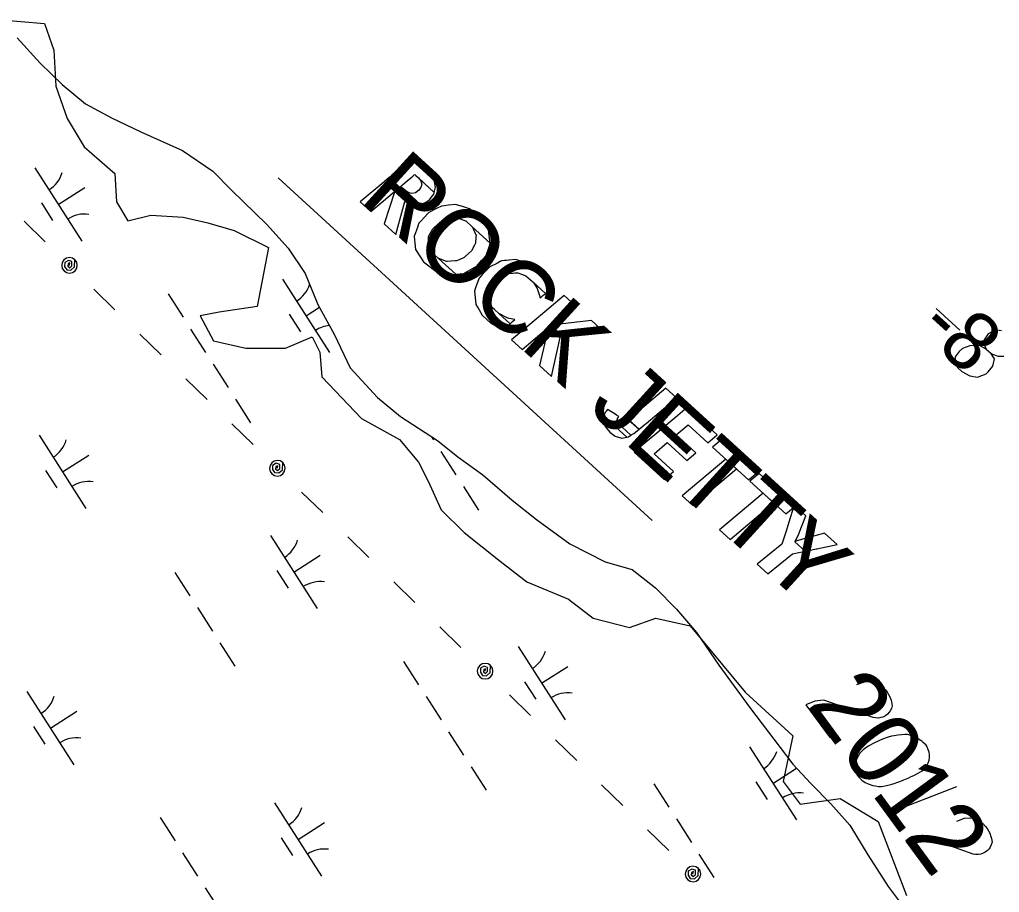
# Model space of a CAD drawing. Extents: x 3962991 to 3983549, y 181631 to 204078.
# Drawn here: x 3976533 to 3977096, y 190286 to 190788 of the extents above; entities that cross this region are included whole.
import ezdxf

# ---------------------------------------------------------------- set-up
doc = ezdxf.new("R2010")
doc.units = 0
for name, color, linetype in [('V-ANNO-MASK', 7, 'Continuous'), ('V-ANNO-MASK2', 7, 'Continuous'), ('V-RIVR-EDGE', 7, 'Continuous'), ('V-RIVR-IDEN', 7, 'Continuous'), ('V-RIVR-RANG', 7, 'Continuous'), ('V-RRAP-FSHR', 7, 'Continuous'), ('V-UTIL-LINE', 7, 'Continuous'), ('V-WETL-SWMP', 7, 'Continuous')]:
    doc.layers.add(name, color=color, linetype=linetype)

msp = doc.modelspace()

# ---------------------------------------------------------------- linework, layer by layer
at = {"layer": 'V-ANNO-MASK2'}
for p, q in [((3977059.67, 190621.74), (3977073.35, 190609.34)), ((3977071.45, 190346.77), (3977030.93, 190331.01))]:
    msp.add_line(p, q, dxfattribs=at)
for points in [[(3976742.01, 190694.45), (3976728.45, 190683.01), (3976734.52, 190677.47), (3976748.08, 190688.91), (3976748.42, 190689.19), (3976755.55, 190682.68), (3976756.57, 190682.19), (3976760.04, 190681.33), (3976763, 190681.68), (3976751.71, 190691.97), (3976751.72, 190691.98), (3976751.91, 190692.14), (3976752.38, 190692.54), (3976752.71, 190692.82), (3976754.11, 190693.99), (3976755.65, 190695.29), (3976755.74, 190695.38), (3976757.37, 190696.74), (3976758.68, 190697.84), (3976758.95, 190698.07), (3976759.55, 190698.57), (3976759.78, 190698.77), (3976759.79, 190698.78), (3976771.03, 190688.53), (3976771.8, 190691.53), (3976770.91, 190695.86), (3976768.19, 190699.86), (3976764.36, 190703.48), (3976758.77, 190708.59), (3976758.68, 190708.52), (3976757.82, 190707.8), (3976755.82, 190706.1), (3976753.71, 190704.33), (3976753.7, 190704.32), (3976753.47, 190704.12), (3976752.87, 190703.61), (3976752.6, 190703.39), (3976751.29, 190702.28), (3976749.67, 190700.92), (3976749.57, 190700.83), (3976748.03, 190699.53), (3976746.64, 190698.36), (3976746.3, 190698.08), (3976745.83, 190697.68), (3976745.65, 190697.52), (3976745.64, 190697.51), (3976743.9, 190696.05), (3976742.58, 190694.94), (3976742.34, 190694.73)], [(3976755.97, 190688.43), (3976754.01, 190689.9), (3976763.02, 190681.68), (3976763.34, 190681.72), (3976764.14, 190681.81), (3976764.53, 190682.04), (3976766.18, 190682.98), (3976768, 190684.03), (3976768.08, 190684.13), (3976768.07, 190684.13), (3976769.41, 190685.75), (3976770.5, 190687.07), (3976770.72, 190687.34), (3976770.94, 190688.19), (3976771.02, 190688.52), (3976761.94, 190696.8), (3976763.32, 190695.13), (3976763.66, 190693.77), (3976763.81, 190693.17), (3976763.32, 190691.31), (3976762.04, 190689.63), (3976761.94, 190689.56), (3976760.28, 190688.36), (3976758.14, 190687.86), (3976757.24, 190688.1)], [(3976760.47, 190698.16), (3976761.95, 190696.8), (3976771.02, 190688.52), (3976771.03, 190688.53)], [(3976748.27, 190688.74), (3976742.24, 190670.43), (3976748.9, 190664.36), (3976754.18, 190683.35), (3976755.55, 190682.68), (3976748.42, 190689.19)], [(3976754, 190689.9), (3976752.6, 190691.16), (3976763, 190681.68), (3976763.02, 190681.68)], [(3976763.16, 190651.2), (3976764.8, 190648.58), (3976771.95, 190643.18), (3976774.95, 190642.38), (3976779.99, 190641.02), (3976783.41, 190641.43), (3976773.5, 190650.47), (3976769.74, 190653.97), (3976767.71, 190658.33), (3976767.71, 190658.45), (3976767.75, 190660.54), (3976767.74, 190660.54), (3976767.79, 190663.18), (3976767.97, 190663.52), (3976768.73, 190664.93), (3976770.18, 190667.62), (3976770.4, 190667.82), (3976770.4, 190667.82), (3976770.92, 190668.3), (3976774.16, 190671.28), (3976774.15, 190671.29), (3976774.21, 190671.33), (3976774.48, 190671.45), (3976777.97, 190673.02), (3976779.16, 190673.55), (3976779.19, 190673.56), (3976782.69, 190673.78), (3976784.3, 190673.88), (3976784.37, 190673.88), (3976789.1, 190672.12), (3976789.13, 190672.11), (3976792.93, 190668.68), (3976803.24, 190659.28), (3976802.71, 190663.76), (3976802.33, 190666.98), (3976799.34, 190671.74), (3976798, 190673.88), (3976797.99, 190673.88), (3976791.23, 190679.14), (3976787.91, 190680.14), (3976783.21, 190681.54), (3976779.29, 190681.12), (3976779.26, 190681.12), (3976779.24, 190681.11), (3976776.74, 190680.84), (3976776.68, 190680.83), (3976775.14, 190680.67), (3976772.74, 190679.44), (3976772.72, 190679.43), (3976771.58, 190678.85), (3976768.24, 190677.14), (3976767.99, 190677.01), (3976767.92, 190676.97), (3976764.93, 190673.77), (3976764.45, 190673.24), (3976764.25, 190673.03), (3976762.23, 190670.85), (3976761.66, 190669.28), (3976761.52, 190668.9), (3976760.79, 190666.89), (3976760.21, 190665.29), (3976760.17, 190665.21), (3976759.49, 190663.31), (3976759.5, 190663.24), (3976759.93, 190659.31), (3976760.34, 190655.7)], [(3976773.62, 190650.43), (3976773.5, 190650.47), (3976783.41, 190641.43), (3976783.48, 190641.44), (3976783.48, 190641.44), (3976785.92, 190641.73), (3976786.04, 190641.74), (3976786.03, 190641.74), (3976788.1, 190641.98), (3976789.93, 190643), (3976790.27, 190643.19), (3976790.26, 190643.19), (3976791.7, 190643.98), (3976794.44, 190645.5), (3976794.71, 190645.65), (3976795.37, 190646.01), (3976798.26, 190649.3), (3976798.31, 190649.35), (3976798.49, 190649.56), (3976800.81, 190652.19), (3976801.24, 190653.42), (3976801.25, 190653.45), (3976802.15, 190656.04), (3976802.55, 190657.23), (3976802.58, 190657.28), (3976803.25, 190659.22), (3976803.24, 190659.24), (3976803.24, 190659.28), (3976792.93, 190668.68), (3976792.95, 190668.62), (3976792.97, 190668.59), (3976795, 190664.19), (3976795.06, 190664.07), (3976794.98, 190662.57), (3976794.81, 190659.32), (3976794.8, 190659.3), (3976794.22, 190658.21), (3976792.52, 190655), (3976792.32, 190654.82), (3976792.27, 190654.76), (3976789.04, 190651.79), (3976788.51, 190651.3), (3976788.22, 190651.17), (3976785.28, 190649.83), (3976783.75, 190649.13), (3976783.24, 190649.1), (3976780.52, 190648.89), (3976778.38, 190648.72), (3976778.16, 190648.8)], [(3976798.66, 190617.87), (3976798.71, 190617.8), (3976803.55, 190613.42), (3976807.98, 190610.81), (3976810.64, 190609.85), (3976810.92, 190609.74), (3976814.61, 190613), (3976808.21, 190618.84), (3976805.67, 190621.22), (3976804.4, 190622.41), (3976803.05, 190625.31), (3976802.37, 190626.77), (3976802.46, 190631.63), (3976803.38, 190633.35), (3976804.85, 190636.06), (3976808.79, 190639.71), (3976808.87, 190639.78), (3976813.82, 190641.99), (3976816.25, 190642.15), (3976817.32, 190642.22), (3976817.73, 190642.24), (3976819.03, 190642.33), (3976821.14, 190641.54), (3976823.79, 190640.55), (3976827.71, 190637.2), (3976835.09, 190630.47), (3976837.28, 190632.25), (3976837.94, 190632.78), (3976836.52, 190636.68), (3976834.32, 190639.86), (3976832.61, 190642.33), (3976832.61, 190642.33), (3976825.85, 190647.59), (3976823.93, 190648.16), (3976819.68, 190649.44), (3976817.83, 190649.99), (3976814.13, 190649.59), (3976813.91, 190649.57), (3976812.51, 190649.42), (3976811.39, 190649.29), (3976810.14, 190649.16), (3976809.76, 190649.11), (3976809.02, 190648.74), (3976807.35, 190647.89), (3976802.63, 190645.47), (3976802.53, 190645.42), (3976798.88, 190641.5), (3976796.85, 190639.3), (3976796.14, 190637.38), (3976794.8, 190633.68), (3976794.57, 190633.05), (3976794.11, 190631.79), (3976794.11, 190631.76), (3976794.11, 190631.69), (3976794.93, 190624.33), (3976794.95, 190624.15), (3976796.83, 190620.97)], [(3976831.56, 190629.23), (3976831.9, 190627.87), (3976832.51, 190628.37), (3976832.74, 190628.56), (3976833.47, 190629.16), (3976834.13, 190629.69), (3976834.96, 190630.37), (3976835.09, 190630.47), (3976827.71, 190637.2), (3976828.04, 190636.68), (3976830.17, 190633.31), (3976830.77, 190631.63), (3976831.43, 190629.74)], [(3976830.72, 190616.59), (3976815.43, 190603.69), (3976821.5, 190598.15), (3976836.8, 190611.05), (3976843.37, 190605.06), (3976843.53, 190605.78), (3976845.03, 190605.94), (3976838.16, 190612.21), (3976851.83, 190623.72), (3976845.75, 190629.26), (3976832.09, 190617.74), (3976831.21, 190617.01)], [(3976808.39, 190618.74), (3976808.21, 190618.84), (3976814.61, 190613), (3976814.64, 190613.04), (3976814.66, 190613.05), (3976815.59, 190613.87), (3976816.06, 190614.29), (3976817.31, 190615.39), (3976814.1, 190616.08), (3976812.89, 190616.34), (3976808.48, 190618.69)], [(3976836.8, 190611.05), (3976831.62, 190588.92), (3976838.46, 190582.69), (3976843.37, 190605.06)], [(3976861.43, 190614.96), (3976838.16, 190612.21), (3976845.03, 190605.94), (3976868.62, 190608.4)], [(3976886.19, 190560.76), (3976882.78, 190557.87), (3976888.83, 190552.35), (3976892.26, 190555.22), (3976892.89, 190555.75), (3976910.28, 190570.41), (3976904.2, 190575.96), (3976886.82, 190561.28)], [(3976891.41, 190543.8), (3976886.06, 190539.28), (3976903.33, 190523.53), (3976908.69, 190528.05), (3976897.44, 190538.31), (3976905, 190544.69), (3976916.25, 190534.43), (3976921.48, 190538.84), (3976910.23, 190549.1), (3976917.05, 190554.85), (3976928.3, 190544.59), (3976933.65, 190549.1), (3976916.39, 190564.84), (3976911.04, 190560.34), (3976904.22, 190554.59), (3976898.98, 190550.18)], [(3976870.32, 190552.72), (3976871.93, 190550.75), (3976875.17, 190548.3), (3976875.64, 190548.16), (3976878.88, 190547.19), (3976879, 190547.22), (3976881.71, 190547.79), (3976868.5, 190559.84), (3976868.34, 190556.94), (3976868.4, 190556.74), (3976869.38, 190553.87)], [(3976868.83, 190560.62), (3976868.49, 190559.85), (3976881.71, 190547.79), (3976882.68, 190547.99), (3976884.07, 190548.89), (3976884.11, 190548.91), (3976876.59, 190555.77), (3976876.19, 190556.77), (3976876.02, 190557.2), (3976876.42, 190558.42), (3976876.45, 190558.51), (3976876.96, 190559.22), (3976877.08, 190559.38), (3976877.26, 190559.62), (3976875.92, 190560.44), (3976875, 190561.01), (3976871.06, 190563.43), (3976870.65, 190563.68), (3976869.95, 190562.74), (3976869.82, 190562.57), (3976869.54, 190562.19), (3976869.52, 190562.16)], [(3976878.12, 190555.01), (3976876.59, 190555.77), (3976884.11, 190548.91), (3976884.52, 190549.17), (3976884.69, 190549.29), (3976885.72, 190549.94), (3976885.79, 190549.99), (3976886.55, 190550.48), (3976886.73, 190550.59), (3976888.83, 190552.35), (3976882.78, 190557.88), (3976880.6, 190556.17), (3976880.44, 190556.05), (3976879.58, 190555.66), (3976879.49, 190555.62), (3976878.32, 190555.1)], [(3976936.46, 190546.54), (3976931.14, 190542.07), (3976951.75, 190523.27), (3976957.07, 190527.75)], [(3976938.67, 190535.2), (3976913.66, 190514.11), (3976919.74, 190508.56), (3976944.76, 190529.66)], [(3976957.9, 190526.99), (3976952.58, 190522.52), (3976973.19, 190503.72), (3976978.51, 190508.19)], [(3976960.11, 190515.65), (3976935.1, 190494.55), (3976941.19, 190489), (3976966.2, 190510.1)], [(3976970.99, 190486.23), (3976956.73, 190474.83), (3976962.82, 190469.27), (3976977.07, 190480.68), (3976977.12, 190480.71), (3976984.34, 190482.24), (3976978.41, 190487.65), (3976979.27, 190489.15), (3976979.32, 190489.28), (3976980.87, 190492.61), (3976980.94, 190492.79), (3976984.73, 190502.52), (3976977.99, 190508.66), (3976974.79, 190498.39), (3976974.73, 190498.21), (3976973.58, 190494.52), (3976973.53, 190494.39), (3976972.98, 190492.6), (3976971.01, 190486.29)], [(3976980.12, 190488.38), (3976978.41, 190487.65), (3976984.34, 190482.24), (3976986.37, 190482.68), (3976986.53, 190482.71), (3976990.75, 190483.6), (3976990.96, 190483.64), (3977002.71, 190486.13), (3976995.54, 190492.66), (3976984.41, 190489.62), (3976984.21, 190489.56), (3976980.25, 190488.43)]]:
    msp.add_lwpolyline(points, close=True, dxfattribs=at)
for points in [[(3977097.27, 190609.01), (3977094.64, 190609.25), (3977091.7, 190608.36), (3977089.52, 190607.13), (3977087.25, 190603.85), (3977086.97, 190601.97), (3977088.44, 190598.49), (3977084.61, 190600.55), (3977079.02, 190600.27), (3977074.8, 190598.76), (3977072.83, 190596.99), (3977070.54, 190594.07), (3977070.53, 190590.52), (3977072.16, 190587.62), (3977074.51, 190585.49), (3977079.11, 190583.1), (3977083.44, 190582.38), (3977088.39, 190584.3), (3977089.64, 190585.29), (3977092.28, 190588.59), (3977093.2, 190592.75), (3977091.18, 190596.01)], [(3977088.44, 190598.49), (3977091.18, 190596.01), (3977092.14, 190595.5), (3977095.37, 190594.35), (3977098.54, 190594.31)], [(3977014.03, 190405.55), (3977018.55, 190407.22), (3977023.31, 190407.43), (3977026.41, 190406.01), (3977028.97, 190404.19), (3977030.6, 190402.52), (3977031.58, 190401.19), (3977033.07, 190398.59), (3977033.71, 190396.6), (3977034.03, 190395.6), (3977034.4, 190393.42), (3977033.92, 190391.84), (3977033.25, 190390.52), (3977032.64, 190389.67), (3977031.77, 190388.62), (3977030.44, 190387.64), (3977028.91, 190386.93), (3977027.91, 190386.61), (3977026.45, 190386.36), (3977024.8, 190386.38), (3977023.41, 190386.59), (3976995.15, 190396.63), (3976989.85, 190396.03), (3976984.8, 190393.97), (3976998.68, 190375.03)], [(3977054.25, 190370.24), (3977053.86, 190370.78), (3977052.42, 190372.18), (3977051.37, 190373.05), (3977050.52, 190373.66), (3977049.01, 190374.6), (3977047.04, 190375.62), (3977045.26, 190376.36), (3977043.22, 190376.92), (3977041.56, 190376.93), (3977039.64, 190376.76), (3977037.72, 190376.58), (3977035.53, 190376.21), (3977034.08, 190375.96), (3977032.08, 190375.32), (3977028.83, 190374.17), (3977024.24, 190372.03), (3977020.65, 190370.22), (3977017.72, 190368.07), (3977015.78, 190366.24), (3977014.16, 190363.41), (3977013.41, 190361.64), (3977012.79, 190359.13), (3977012.89, 190356.75), (3977013.21, 190355.75), (3977014.12, 190353.96), (3977015.1, 190352.62), (3977016.93, 190350.68), (3977018.83, 190349.21), (3977020.61, 190348.46), (3977023.31, 190347.57), (3977024.7, 190347.36), (3977026.54, 190347.07), (3977028.2, 190347.05), (3977029.39, 190347.11), (3977031.11, 190347.55), (3977031.84, 190347.67), (3977033.57, 190348.12), (3977035.56, 190348.76), (3977037.55, 190349.4), (3977038.81, 190349.91), (3977039.81, 190350.23), (3977041.07, 190350.75), (3977043.86, 190351.97), (3977045.39, 190352.68), (3977046.92, 190353.39), (3977048.98, 190354.49), (3977051.58, 190355.99), (3977052.38, 190356.57), (3977053.25, 190357.62), (3977054.12, 190358.67), (3977055.14, 190360.64), (3977055.62, 190362.23), (3977055.83, 190363.61), (3977055.85, 190365.27), (3977055.6, 190366.72), (3977055.28, 190367.72), (3977054.96, 190368.71), (3977054.25, 190370.24)], [(3977071.5, 190327.12), (3977076.02, 190328.79), (3977080.78, 190329), (3977083.87, 190327.58), (3977086.43, 190325.77), (3977088.07, 190324.09), (3977089.05, 190322.76), (3977090.54, 190320.16), (3977091.18, 190318.17), (3977091.5, 190317.18), (3977091.87, 190314.99), (3977091.39, 190313.41), (3977090.71, 190312.09), (3977090.11, 190311.24), (3977089.24, 190310.19), (3977087.9, 190309.21), (3977086.37, 190308.5), (3977085.38, 190308.18), (3977083.92, 190307.94), (3977082.27, 190307.95), (3977080.88, 190308.17), (3977052.62, 190318.21), (3977047.32, 190317.6), (3977042.27, 190315.54), (3977056.15, 190296.6)]]:
    msp.add_lwpolyline(points, dxfattribs=at)
at = {"layer": 'V-RIVR-EDGE'}
msp.add_lwpolyline([(3976519.55, 190787.85), (3976546.85, 190785.66), (3976552.31, 190770.37), (3976553.4, 190749.62), (3976559.96, 190731.05), (3976569.78, 190714.67), (3976587.26, 190699.38), (3976588.35, 190683), (3976594.9, 190672.08), (3976608.01, 190675.35), (3976626.58, 190674.26), (3976640.77, 190670.99), (3976656.06, 190666.62), (3976675.72, 190656.79), (3976669.17, 190622.93), (3976647.33, 190619.65), (3976636.41, 190617.47), (3976644.05, 190603.27), (3976662.62, 190598.9), (3976685.55, 190598.9), (3976700.84, 190605.46), (3976705.21, 190596.72), (3976706.3, 190582.52), (3976729.24, 190558.49), (3976751.08, 190546.48), (3976762, 190533.37), (3976767.46, 190522.45), (3976775.11, 190506.07), (3976788.22, 190492.96), (3976808.97, 190476.58), (3976824.26, 190464.57), (3976848.28, 190454.74), (3976862.48, 190443.82), (3976883.23, 190438.36), (3976898.52, 190443.82), (3976918.18, 190439.45), (3976949.85, 190401.22), (3976977.16, 190376.1), (3976971.7, 190349.89), (3976981.53, 190336.79), (3977004.46, 190340.06), (3977026.31, 190326.96), (3977042.69, 190284.36)], dxfattribs=at)
at = {"layer": 'V-RRAP-FSHR'}
msp.add_line((3976681.21, 190696.92), (3976896.29, 190500), dxfattribs=at)
at = {"layer": 'V-UTIL-LINE'}
for points in [[(3976535.19, 190672.04), (3976547.35, 190660.17)], [(3976561.28, 190646.58), (3976561.52, 190647.99), (3976560.47, 190647.5), (3976560.27, 190646.14), (3976561.42, 190645.24), (3976562.67, 190646.39), (3976562.7, 190648.74), (3976560.69, 190649.46), (3976558.59, 190648.23), (3976558.5, 190645.94), (3976559.72, 190644.07), (3976562.13, 190643.87), (3976564.16, 190645.73), (3976564.42, 190649.8), (3976562.95, 190650.76), (3976561.22, 190651.08), (3976559.5, 190650.71), (3976558.05, 190649.72), (3976557.1, 190648.25), (3976556.78, 190646.52), (3976557.14, 190644.8), (3976558.13, 190643.36), (3976559.6, 190642.4), (3976561.33, 190642.08), (3976563.05, 190642.44), (3976564.5, 190643.43), (3976565.45, 190644.9), (3976565.78, 190646.63), (3976565.41, 190648.35), (3976564.42, 190649.8)], [(3976575.27, 190632.93), (3976587.43, 190621.05)], [(3976601.75, 190607.09), (3976613.91, 190595.21)], [(3976628.23, 190581.25), (3976640.4, 190569.37)], [(3976654.71, 190555.4), (3976666.88, 190543.53)], [(3976680.8, 190529.94), (3976681.04, 190531.36), (3976679.98, 190530.86), (3976679.79, 190529.5), (3976680.94, 190528.6), (3976682.19, 190529.76), (3976682.22, 190532.1), (3976680.21, 190532.82), (3976678.11, 190531.59), (3976678.02, 190529.31), (3976679.24, 190527.44), (3976681.65, 190527.24), (3976683.68, 190529.09), (3976683.94, 190533.16), (3976682.47, 190534.12), (3976680.74, 190534.44), (3976679.02, 190534.08), (3976677.57, 190533.08), (3976676.62, 190531.61), (3976676.3, 190529.89), (3976676.66, 190528.17), (3976677.65, 190526.72), (3976679.12, 190525.76), (3976680.85, 190525.44), (3976682.57, 190525.8), (3976684.02, 190526.8), (3976684.97, 190528.27), (3976685.29, 190530), (3976684.93, 190531.71), (3976683.94, 190533.16)], [(3976694.79, 190516.29), (3976706.96, 190504.42)], [(3976721.27, 190490.45), (3976733.44, 190478.58)], [(3976747.75, 190464.61), (3976759.92, 190452.74)], [(3976774.23, 190438.77), (3976786.4, 190426.9)], [(3976800.31, 190413.3), (3976800.56, 190414.72), (3976799.5, 190414.22), (3976799.31, 190412.86), (3976800.46, 190411.96), (3976801.71, 190413.12), (3976801.74, 190415.47), (3976799.73, 190416.18), (3976797.63, 190414.96), (3976797.54, 190412.67), (3976798.76, 190410.8), (3976801.17, 190410.6), (3976803.2, 190412.45), (3976803.46, 190416.52), (3976801.99, 190417.48), (3976800.26, 190417.8), (3976798.54, 190417.44), (3976797.09, 190416.45), (3976796.14, 190414.97), (3976795.81, 190413.25), (3976796.18, 190411.53), (3976797.17, 190410.08), (3976798.64, 190409.13), (3976800.37, 190408.8), (3976802.09, 190409.17), (3976803.54, 190410.16), (3976804.49, 190411.63), (3976804.81, 190413.36), (3976804.45, 190415.08), (3976803.46, 190416.52)], [(3976814.31, 190399.66), (3976826.48, 190387.78)], [(3976840.79, 190373.81), (3976852.96, 190361.94)], [(3976867.27, 190347.97), (3976879.44, 190336.1)], [(3976893.75, 190322.13), (3976905.92, 190310.26)], [(3976919.83, 190296.67), (3976920.08, 190298.09), (3976919.02, 190297.59), (3976918.83, 190296.23), (3976919.98, 190295.33), (3976921.23, 190296.49), (3976921.25, 190298.83), (3976919.25, 190299.55), (3976917.15, 190298.32), (3976917.06, 190296.03), (3976918.28, 190294.16), (3976920.69, 190293.96), (3976922.72, 190295.82), (3976922.98, 190299.89), (3976921.51, 190300.85), (3976919.78, 190301.17), (3976918.06, 190300.8), (3976916.61, 190299.81), (3976915.66, 190298.34), (3976915.33, 190296.61), (3976915.7, 190294.89), (3976916.69, 190293.45), (3976918.16, 190292.49), (3976919.89, 190292.17), (3976921.61, 190292.53), (3976923.05, 190293.52), (3976924.01, 190295), (3976924.33, 190296.72), (3976923.97, 190298.44), (3976922.98, 190299.89)]]:
    msp.add_lwpolyline(points, dxfattribs=at)
at = {"layer": 'V-WETL-SWMP'}
for p, q in [((3976541.36, 190702.61), (3976568.35, 190660.52)), ((3976554.86, 190681.57), (3976570.01, 190691.28)), ((3976545.12, 190682.45), (3976551.6, 190672.35)), ((3976683.81, 190638.66), (3976710.8, 190596.57)), ((3976617.93, 190630.19), (3976626.57, 190616.72)), ((3976697.3, 190617.62), (3976705.03, 190622.57)), ((3976687.57, 190618.5), (3976694.05, 190608.4)), ((3976630.88, 190609.98), (3976639.52, 190596.51)), ((3976643.84, 190589.78), (3976652.47, 190576.31)), ((3976656.79, 190569.57), (3976665.43, 190556.1)), ((3976543.78, 190548.89), (3976570.77, 190506.8)), ((3976769.51, 190548), (3976770.57, 190546.35)), ((3976557.27, 190527.84), (3976572.43, 190537.56)), ((3976774.88, 190539.62), (3976783.52, 190526.15)), ((3976547.54, 190528.73), (3976554.02, 190518.63)), ((3976787.84, 190519.41), (3976796.47, 190505.94)), ((3976676.8, 190491.35), (3976703.79, 190449.25)), ((3976690.3, 190470.3), (3976705.45, 190480.01)), ((3976621.9, 190470.05), (3976630.53, 190456.58)), ((3976680.56, 190471.19), (3976687.04, 190461.08)), ((3976634.85, 190449.85), (3976643.49, 190436.38)), ((3976647.81, 190429.64), (3976656.44, 190416.17)), ((3976819.25, 190427.4), (3976846.24, 190385.3)), ((3976753.37, 190418.92), (3976762.01, 190405.45)), ((3976832.75, 190406.35), (3976847.9, 190416.06)), ((3976823.01, 190407.24), (3976829.49, 190397.13)), ((3976536.77, 190401.57), (3976563.76, 190359.48)), ((3976766.33, 190398.72), (3976774.96, 190385.25)), ((3976550.27, 190380.53), (3976565.42, 190390.24)), ((3976540.53, 190381.41), (3976547.01, 190371.31)), ((3976779.28, 190378.51), (3976787.91, 190365.04)), ((3976952.28, 190369.85), (3976979.26, 190327.76)), ((3976792.23, 190358.31), (3976800.87, 190344.84)), ((3976965.77, 190348.81), (3976979.37, 190357.52)), ((3976897.37, 190348.56), (3976906.01, 190335.09)), ((3976956.04, 190349.69), (3976962.51, 190339.59)), ((3976679.22, 190337.62), (3976706.21, 190295.53)), ((3976613.34, 190329.15), (3976621.98, 190315.68)), ((3976910.33, 190328.35), (3976918.96, 190314.88)), ((3976692.71, 190316.58), (3976707.87, 190326.29)), ((3976682.98, 190317.46), (3976689.46, 190307.36)), ((3976626.29, 190308.94), (3976634.93, 190295.47)), ((3976923.28, 190308.15), (3976931.91, 190294.68)), ((3976639.25, 190288.74), (3976647.88, 190275.27))]:
    msp.add_line(p, q, dxfattribs=at)
msp.add_lwpolyline([(3976531.13, 190777.45), (3976544.46, 190762.82), (3976557.16, 190750.56), (3976570.43, 190739.5), (3976585.43, 190731.44), (3976602.22, 190723.42), (3976626.19, 190712.54), (3976643.63, 190700.73), (3976654.52, 190689.74), (3976674.84, 190670.01), (3976686.97, 190656.55), (3976696.73, 190641.86), (3976704.18, 190624.16), (3976713.39, 190607.08), (3976722.65, 190587.63), (3976738.4, 190570.67), (3976751.68, 190559.61), (3976772.84, 190545.83), (3976784.54, 190536.53), (3976798.98, 190526.08), (3976815.88, 190511.52), (3976829.75, 190500.47), (3976849.01, 190486.54), (3976869.41, 190476.2), (3976884.94, 190471.72), (3976898.2, 190461.25), (3976910.3, 190448.98), (3976921.83, 190435.51), (3976934.65, 190416.72), (3976952.31, 190392.66), (3976977.25, 190359.81), (3976987.55, 190348.7), (3976999.05, 190337.01), (3977009.97, 190324.72), (3977020.37, 190307.66), (3977031.99, 190289.44), (3977043.55, 190274.19)], dxfattribs=at)
for centre, start, end in [((3976540.15, 190704.95), 301.8919, 343.4355), ((3976569.96, 190658.44), 81.8919, 123.4355), ((3976682.6, 190641), 301.8919, 342.1345), ((3976712.41, 190594.49), 95.5013, 123.4355), ((3976542.57, 190551.22), 301.8919, 343.4355), ((3976572.38, 190504.72), 81.8919, 123.4355), ((3976675.59, 190493.68), 301.8919, 343.4355), ((3976705.4, 190447.17), 81.8919, 123.4355), ((3976818.04, 190429.73), 301.8919, 343.4355), ((3976535.56, 190403.91), 301.8919, 343.4355), ((3976847.85, 190383.22), 81.8919, 123.4355), ((3976565.37, 190357.4), 81.8919, 123.4355), ((3976951.06, 190372.19), 301.8919, 343.4355), ((3976980.88, 190325.68), 81.8919, 123.4355), ((3976678.01, 190339.96), 301.8919, 343.4355), ((3976707.82, 190293.45), 81.8919, 123.4355)]:
    msp.add_arc(centre, 17.62, start, end, dxfattribs=at)

# ---------------------------------------------------------------- texts
at = {"layer": 'V-ANNO-MASK'}
for s, height, rotation, p in [('ROCK JETTY', 42, 317.6368, (3976727.18, 190684.17)), ('-8', 33.5, 317.7841, (3977048.33, 190609.24)), ('2012', 42, 306.2319, (3976984.8, 190393.97))]:
    msp.add_text(s, height=height, rotation=rotation, dxfattribs=at).set_placement(p)
at = {"layer": 'V-RIVR-IDEN'}
for s, rotation, p in [('ROCK JETTY', 317.6368, (3976727.18, 190684.17)), ('2012', 306.2319, (3976984.8, 190393.97))]:
    msp.add_text(s, height=42, rotation=rotation, dxfattribs=at).set_placement(p)
at = {"layer": 'V-RIVR-RANG'}
msp.add_text('-8', height=33.5, rotation=317.7841, dxfattribs=at).set_placement((3977048.33, 190609.24))

doc.saveas('drawing.dxf')
